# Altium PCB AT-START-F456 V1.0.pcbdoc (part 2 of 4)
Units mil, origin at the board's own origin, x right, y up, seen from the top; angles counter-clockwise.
Board outline 10942.5 x 3554 mil, 2 copper layers (Top Layer, Bottom Layer); 156 components, 201 nets, 759 pads, 796 vias.
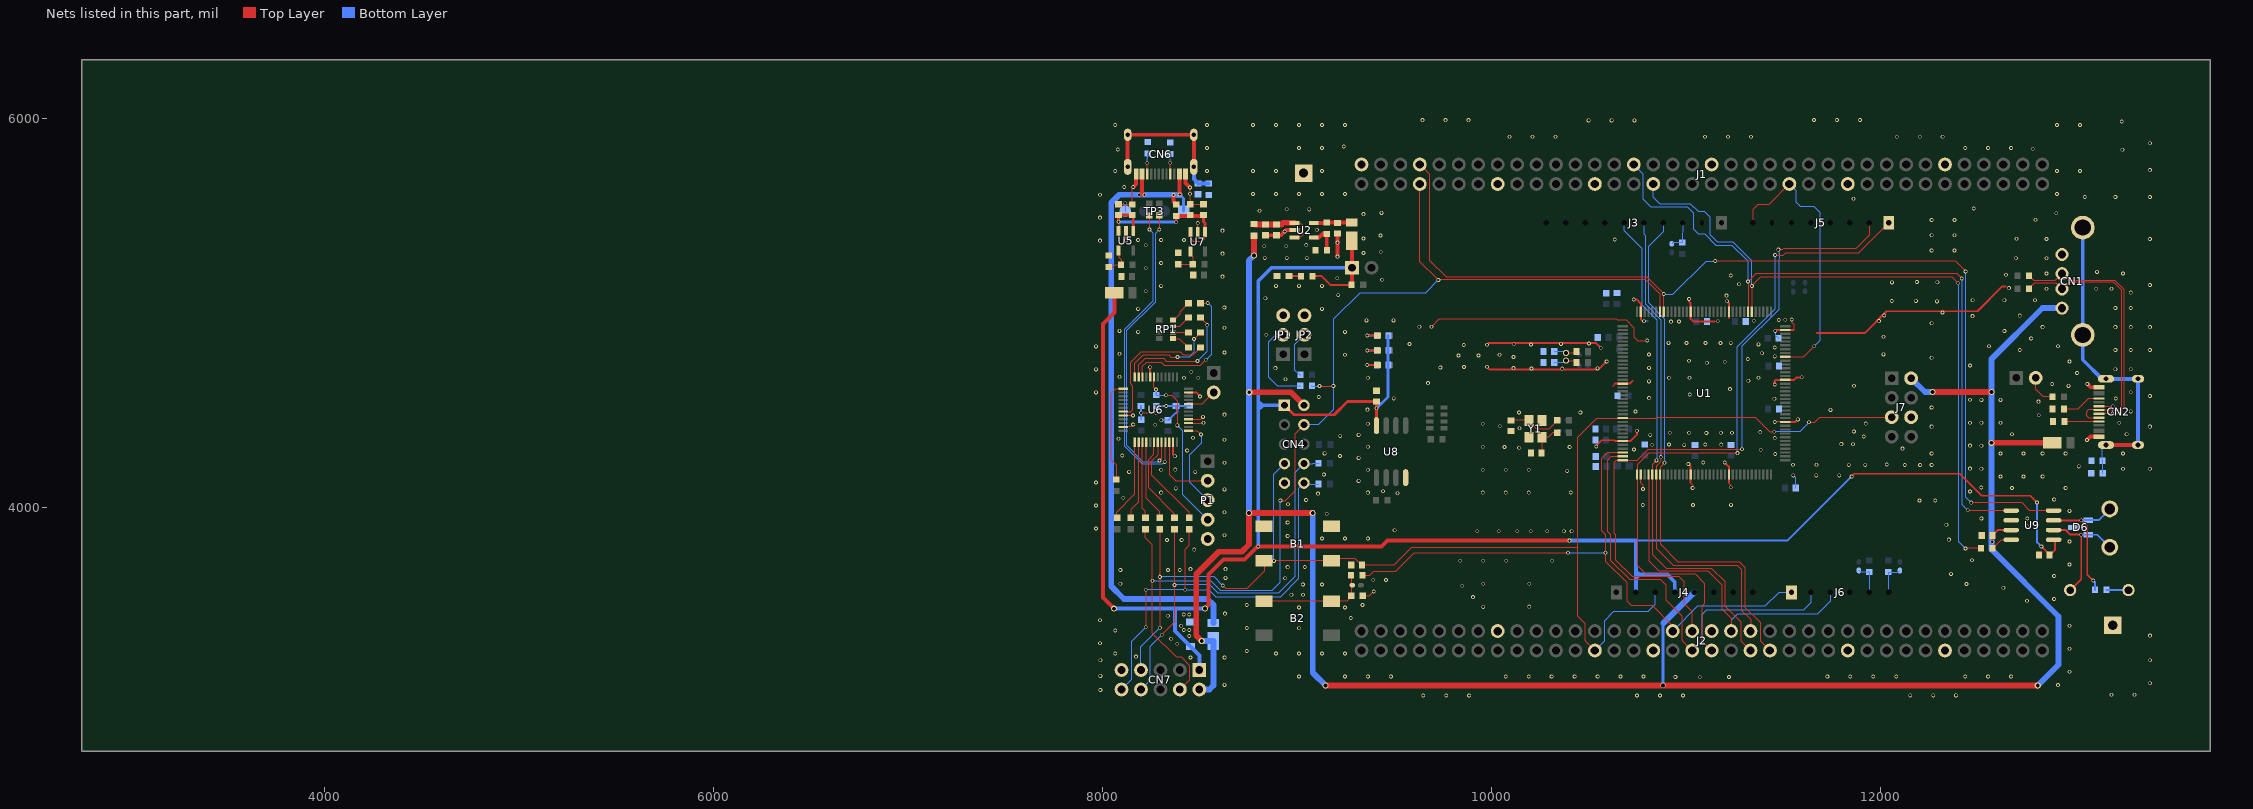
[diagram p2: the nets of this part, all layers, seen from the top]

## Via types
v1: diameter 19.7, hole 11.8, Top Layer to Bottom Layer, 419 vias
v2: diameter 19.68, hole 11.81, Top Layer to Bottom Layer, 364 vias
v3: diameter 31.5, hole 19.68, Top Layer to Bottom Layer, 12 vias
v4: diameter 27.56, hole 19.68, Top Layer to Bottom Layer, 1 vias

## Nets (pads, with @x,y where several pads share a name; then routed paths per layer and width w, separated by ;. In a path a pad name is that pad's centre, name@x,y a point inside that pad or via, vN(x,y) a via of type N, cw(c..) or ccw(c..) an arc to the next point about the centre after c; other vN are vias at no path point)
3V3: C13.1 C42.2 CN4.1 CN7.1 D1.1 D4.1 D5.1 J4.2 J4.4 JP3.1 R10.1 R17.1 R26.1 R27.1 R28.1 U8.8 U9.5 | length 11760.2
  Top Layer w10: R10.1@9075.76,5191.98 9124.16,5191.98 9169.26,5146.98 R17.1@9280.76,5146.98 ; v2(11848.96,4161.95) 11862.88,4175.87 12405.37,4175.87 12518.62,4062.61 12767.57,4062.61 v2(12802.57,4027.61) ; v2(12824.49,3801.51) 12825.48,3801.51 12860.91,3766.07 12860.91,3763.12 C42.2@12866.82,3757.22 12895.36,3785.76 12895.36,3828.97 U9.5@12887.72,3836.61
  Top Layer w15: CN4.1@8933.26,4527.98 8980.46,4480.48 9189.26,4479.18 9257.66,4547.38 9406.16,4547.38 9406.16,4512.98 9406.76,4512.38 U8.8@9406.16,4423.68
  Top Layer w20: v3(8056.02,3482.17) 7999.57,3538.62 7999.57,4945.41 8058.76,5004.61 D5.1@8058.76,5091.44 ; D5.1@8058.76,5107.05 D5.1@8058.76,5091.44 ; D5.1@8078.86,5111.53 D5.1@8058.76,5091.44 ; v3(8524.32,3482.61) 8542.32,3500.61 8542.32,3657.37 8620.57,3735.61 8728.41,3735.61 8794.76,3801.97 v2(8798.21,3801.97) 9432.21,3801.97 9462.21,3831.97 v2(10398.21,3831.97) ; D1.1@9280.21,5373.23 JP3.1@9280.21,5234.97 9280.16,5147.48 R17.1@9280.76,5146.98
  Bottom Layer w10: 10739.86,3831.98 11518.99,3831.98 v2(11848.96,4161.95) ; v2(12802.57,4027.61) 12802.57,3823.43 v2(12824.49,3801.51)
  Bottom Layer w15: v2@9406.76,4512.38 9465.36,4571.08 R28.1@9465.36,4886.28
  Bottom Layer w20: v3(8056.02,3482.17) 8056.47,3482.61 8362.66,3482.61 ; CN7.1@8495.46,3166.58 8495.46,3241.74 D4.1@8449.57,3287.62 8370.57,3366.62 8370.57,3474.71 8362.66,3482.61 ; v3(8524.32,3482.61) 8362.66,3482.61 ; v2@8798.26,3801.98 8798.26,4505.87 ; CN4.1@8933.26,4527.98 8817.56,4528.58 ; JP3.1@9280.21,5234.97 8867.26,5234.98 8798.26,5165.98 8798.26,4547.88 ; v2@10398.26,3831.98 10739.86,3831.98 10739.86,3674.68 ; J4.2@10739.86,3565.98 10739.86,3638.78 ; J4.4@10939.86,3565.98 10939.86,3619.38 10902.26,3656.98 10757.56,3656.98 ; 8798.26,4505.87 8817.56,4525.17 8817.56,4528.58 ; 8798.26,4505.87 8798.26,4547.88 ; 8798.26,4547.88 8817.56,4528.58 ; 10739.86,3638.78 10757.56,3656.98 ; 10739.86,3638.78 10739.86,3674.68 ; 10739.86,3674.68 10757.56,3656.98
  other v2: 9406.72,4512.39
5V: C41.2 CN1.1 CN4.2 CN7.2 D2.1 D3.1 F1.1 J4.5 J7.2 U9.3 | length 11648.9
  Top Layer w10: v2(12572.57,3826.61) 12573.13,3827.17 C41.2@12573.13,3858.61 12573.13,3860.58 12599.16,3886.61 U9.3@12669.42,3886.61
  Top Layer w30: v3(8507.66,3316.18) 8479.57,3344.27 8479.57,3658.61 8595.57,3774.61 8713.57,3774.61 8751.21,3812.25 v3(8751.21,3973.97) v3(9078.21,3973.97) ; v3(8752.21,4594.97) 8966.24,4594.97 CN4.2@9033.23,4527.98 ; v3@8776.26,5297.98 F1.1@8776.26,5399.98 ; v3(9144.75,3086.78) v3(12805.73,3086.78) ; v3@12263.57,4596.61 v3(12264.57,4595.61) v3(12567.57,4595.61) ; v3(12567.77,4334.82) 12879.89,4334.82 D2.1@12880.89,4335.82
  Bottom Layer w15: v4(10879.57,3087.61) 10879.26,3087.93 10879.26,3404.98 10881.26,3406.98
  Bottom Layer w30: CN7.2@8495.46,3066.58 8547.53,3066.58 8567.57,3086.61 D3.1@8567.57,3315.86 8507.97,3315.86 v3(8507.66,3316.18) ; v3(8751.21,3973.97) 8751.21,5272.97 v3(8776.21,5297.97) ; v3@9078.21,3973.93 9078.21,3153.33 v3(9144.75,3086.78) ; 10881.26,3406.98 J4.5@11039.86,3565.98 ; J7.2@12154.81,4666.56 12225.75,4595.61 v3(12264.57,4595.61) ; v3(12805.73,3086.78) 12912.57,3193.61 12912.57,3442.42 12567.77,3787.22 v3(12567.77,4334.82) 12567.57,4335.02 v3(12567.57,4595.61) 12567.57,4764.6 12830.47,5027.5 CN1.1@12930.72,5027.5
$2N452: C1.2 R1.1 Y1.1 | length 279.2
  Top Layer w6: C1.2@10097.57,4450.17 10097.82,4449.92 Y1.1@10190.1,4449.92 10190.1,4445.99 10231.48,4404.61 10291.04,4404.61 10335.91,4449.48 R1.1@10335.91,4450.61
$2N453: C2.2 R3.1 Y1.3 | length 170
  Top Layer w6: C2.2@10255.13,4282.61 10257.03,4284.52 Y1.3@10257.03,4363.3 10288.26,4363.3 10311.57,4386.61 R3.1@10335.91,4386.61
$2N511: C3.2 R5.1 X1.1 | length 120.3
  Top Layer w5.98: X1.1@10380.73,4796.85 10426.66,4796.85 R5.1@10434.27,4804.45
  Bottom Layer w5.98: C3.2@10319.95,4803.64 10373.94,4803.64 X1.1@10380.73,4796.85
$2N512: C4.2 R6.1 X1.2 | length 122.2
  Top Layer w5.98: X1.2@10380.73,4757.48 10424.51,4757.48 R6.1@10434.27,4747.72
  Bottom Layer w5.98: C4.2@10319.96,4748.08 10371.34,4748.08 X1.2@10380.73,4757.48
$2N701: JP1.2 R13.1 | length 455.4
  Bottom Layer w6: JP1.2@8926.26,4889.98 8887.16,4889.98 8850.26,4852.98 8850.26,4674.98 8897.16,4627.98 R13.1@9016.76,4627.98
$2N702: JP2.2 R14.1 | length 244.9
  Bottom Layer w6: R14.1@9017.76,4683.98 9011.76,4683.98 8984.26,4711.48 8984.26,4837.98 JP2.2@9036.26,4889.98
$3N58: C5.1 C6.1 F1.2 U2.1 U2.3 | length 369.5
  Top Layer w6: U2.1@8971.16,5465.98 9014.56,5464.58 9026.26,5452.98 9026.26,5402.98 9014.16,5390.98 U2.3@8984.26,5390.98
  Top Layer w30: F1.2@8776.26,5459.28 8778.36,5457.08 8836.21,5457.08 8891.21,5457.08 8917.86,5457.08 8926.66,5465.98 8971.16,5465.98 U2.1@8984.26,5465.98
$3N81: R15.1 R16.1 U2.4 | length 160.8
  Top Layer w20: U2.4@9084.26,5390.98 9111.16,5390.98 9130.76,5410.48 9150.26,5410.48 9150.26,5324.48 R15.1@9149.66,5323.98
$3N82: C7.1 D1.2 R16.2 U2.5 | length 196.6
  Top Layer w20: U2.5@9084.26,5465.98 9114.76,5465.98 9115.16,5465.48 9150.16,5465.48 9151.46,5466.68 D1.2@9280.21,5466.73
$3N119: LED1.1 R10.2 | length 64.5
  Top Layer w10: LED1.1@8956.26,5192.78 R10.2@9020.76,5191.98
$3N184: B2.2 B2.4 R18.2 R19.1 R20.1 | length 568
  Top Layer w6: B2.4@8828.03,3521.56 B2.2@9174.49,3521.56 9252.26,3521.58 9278.66,3547.98 9277.66,3548.98 R19.1@9277.66,3653.98
$3N504: LED2.1 R26.2 | length 104.4
  Top Layer w10: v2@9358.66,4734.58 9359.26,4735.18 LED2.1@9411.01,4735.2
  Bottom Layer w10: v2@9358.66,4734.58 9359.06,4734.98 R26.2@9410.36,4734.98
  other v2: 9358.65,4734.61
$3N505: LED3.1 R27.2 | length 104.1
  Top Layer w10: v2@9358.66,4809.98 LED3.1@9411.06,4810.18
  Bottom Layer w10: v2@9358.66,4809.98 R27.2@9410.36,4809.98
  other v2: 9358.65,4810
$3N506: LED4.1 R28.2 | length 104.1
  Top Layer w10: v2@9358.66,4886.28 LED4.1@9411.06,4886.48
  Bottom Layer w10: v2@9358.66,4886.28 R28.2@9410.36,4886.28
  other v2: 9358.65,4886.3
$3N17443: CN2.B5 R33.2 | length 202.1
  Top Layer w6: R33.2@12941.23,4508.61 13010.57,4508.61 13064.67,4562.72 CN2.B5@13120.94,4562.72
$3N17484: CN2.A5 R32.2 | length 177.7
  Top Layer w5.98: R32.2@12943.23,4444.61 CN2.A5@13120.94,4444.62
$3N17593: JP4.2 R34.1 | length 159.9
  Top Layer w5.98: JP4.2@12795.57,4668.61 12795.57,4611 12833.95,4572.61 R34.1@12881.91,4572.61
$3N25576: R90.2 U9.4 | length 114.4
  Top Layer w5.98: R90.2@12573.23,3792.61 12575.57,3792.61 12619.57,3836.61 U9.4@12669.42,3836.61
$3N25805: R89.1 SW1.2 | length 112.8
  Bottom Layer w10: R89.1@13160.23,3578.61 13271.57,3578.61 SW1.2@13272.57,3577.61
$4N269: J6.5 R56.2 R57.2 | length 163
  Bottom Layer w6: R56.2@11886.26,3678.68 11892.46,3672.48 11940.16,3672.48 J6.5@11939.86,3565.98
$4N270: J6.6 R58.2 R59.2 | length 168.5
  Bottom Layer w6: J6.6@12039.8,3565.97 12039.81,3667.56 R59.2@12037.06,3670.3 12089.36,3670.3 R58.2@12096.95,3677.89
$4N339: J3.3 R60.1 R61.2 | length 161.8
  Bottom Layer w6: R60.1@10926.16,5357.28 10926.16,5362.48 10979.26,5362.48 J3.3@10979.86,5465.98
$6N792: LD1.1 RP1.8 | length 121.7
  Top Layer w6: RP1.8@8360.2,4965.45 8363.16,4965.45 8397.25,4999.55 8397.25,5009.62 8439.43,5051.8 LD1.1@8439.43,5052.63
$6N793: LD2.1 RP1.7 | length 98.6
  Top Layer w6: RP1.7@8360.2,4933.96 8393.82,4933.96 8438.39,4978.53 LD2.1@8440.39,4978.53
$6N794: LD3.1 RP1.6 | length 80.6
  Top Layer w6: RP1.6@8360.2,4902.46 8415.6,4902.46 8416.43,4901.63 LD3.1@8440.43,4901.63
$6N795: LD4.1 RP1.5 | length 99
  Top Layer w6: RP1.5@8360.2,4870.97 8393.05,4870.97 8438.39,4825.63 LD4.1@8440.39,4825.63
$6N16959: C15.2 C16.2 C18.2 C19.2 F2.2 U5.1 U5.3 U7.1 U7.3 | length 955.4
  Top Layer w6: v2(8079.97,5471.01) 8079.97,5424.64 U5.3@8080.56,5424.05 ; U7.3@8449.34,5418.39 8449.34,5386.85 8465.17,5371.01 8510.77,5371.01 8524.34,5384.58 U7.1@8524.34,5418.39
  Top Layer w15: v2(8079.97,5471.01) 8079.97,5504.25 8077.97,5506.25 8149.57,5506.25 C19.2@8150.37,5505.45 8155.56,5500.26 U5.1@8155.56,5424.05 ; v2(8376.76,5469.02) 8376.76,5500.59 F2.2@8377.56,5501.39 ; C16.2@8517.56,5506.49 8517.56,5471.42 8524.34,5464.65 U7.1@8524.34,5418.39
  Top Layer w20: F2.2@8377.56,5501.39 8512.46,5501.39 C16.2@8517.56,5506.49
  Bottom Layer w15: v2(8079.97,5471.01) 8081.17,5469.81 8375.97,5469.81 v2(8376.76,5469.02)
$6N17598: R43.2 R49.1 U7.4 | length 144.7
  Top Layer w6: R49.1@8387.57,5252.95 8439.57,5252.95 8440.03,5253.41 R43.2@8461.9,5253.41 8461.9,5290.28 8449.34,5302.85 U7.4@8449.34,5318.39
$6N17675: R50.2 R51.1 U5.4 | length 146.5
  Top Layer w6: R51.1@8029.57,5238.95 8052.89,5238.95 8064.98,5251.05 R50.2@8092.9,5251.05 8092.9,5275.68 8080.56,5288.02 U5.4@8080.56,5324.05
ATLINK_5V: CN6.A4B9 CN6.B4A9 D3.2 F2.1 TP3.1 | length 3362.8
  Top Layer w20: CN6.B4A9@8200.71,5717.9 8200.71,5609.88 8201.17,5609.41 ; v2(8362.76,5609.37) 8362.76,5575.52 F2.1@8377.56,5560.71 ; CN6.A4B9@8393.71,5717.9 8394.27,5717.34 v2(8394.27,5611.13)
  Bottom Layer w15: v2(8394.27,5611.13) 8414.58,5590.82 TP3.1@8414.58,5526.61
  Bottom Layer w30: v2(8394.27,5611.13) 8392.51,5609.37 v2(8362.76,5609.37) 8361.51,5610.61 v2(8213.24,5610.61) v2(8186.47,5610.61) 8083.57,5610.61 8042.25,5569.3 8042.25,3597.93 8108.3,3531.88 8537.57,3531.88 8567.57,3501.88 D3.2@8567.57,3409.36
ATLK_BOOT0: R45.1 U6.27 | length 395.7
  Top Layer w6: U6.27@8203.01,4337.98 8202.96,3998.78 8218.46,3983.38 R45.1@8218.46,3948.68
ATLK_NRST: R46.1 U6.28 | length 419.2
  Top Layer w6: U6.28@8222.69,4337.98 8222.66,4049.48 8292.46,3979.78 R46.1@8292.46,3947.68
ATLK_RX: CN4.10 CN7.10 R25.1 R48.2 | length 2281.5
  Top Layer w6: v2(8219.86,3386.38) 8219.86,3578.78 v2(8220.26,3579.18) ; v2@8425.16,3576.68 v2(8422.66,3579.18) 8422.66,3788.08 8443.66,3809.08 R48.2@8443.66,3892.68
  Bottom Layer w6: CN7.10@8095.46,3066.58 8145.96,3117.18 8145.96,3312.48 v2(8219.86,3386.38) ; v2(8220.26,3579.18) v2(8422.66,3579.18) 8545,3579.18 8579.46,3544.73 8913.43,3544.73 9007.59,3638.89 9007.59,4102.34 CN4.10@9033.23,4127.98 ; CN4.10@9061.16,4128.18 9066.16,4123.08 R25.1@9110.16,4123.08
ATLK_SWCLK: R41.1 U6.25 | length 427
  Top Layer w6: R41.1@8070.46,3949.58 8070.46,3979.08 8163.66,4072.28 U6.25@8163.66,4337.98
ATLK_SWDIO: R44.1 U6.26 | length 404.5
  Top Layer w6: R44.1@8144.46,3949.58 8144.46,3993.08 8183.36,4031.98 U6.26@8183.36,4337.98
ATLK_SWO: R52.1 U6.13 | length 530.4
  Top Layer w6: R52.1@8070.26,4142.58 8070.26,4218.73 8042.65,4246.34 8042.65,4589.69 8066.53,4613.58 U6.13@8104.58,4613.57
ATLK_TX: CN4.8 CN7.8 R24.1 R47.2 | length 2247.2
  Top Layer w6: v2(8302.46,3348.18) 8367.5,3413.22 v2(8367.5,3603.41) 8367.5,3846.62 8367.66,3846.78 R47.2@8367.66,3892.68
  Bottom Layer w6: CN7.8@8195.43,3066.63 8244,3115.2 8244,3289.72 v2(8302.46,3348.18) ; v2(8367.5,3603.41) 8368.11,3604.03 8550.15,3604.03 8592.12,3562.06 8900.43,3562.06 8985.14,3646.77 8985.14,4179.88 CN4.8@9033.23,4227.98 ; CN4.8@9033.26,4227.98 9078.86,4227.98 9080.96,4229.98 R24.1@9110.76,4229.98
BOOT0: CN4.4 CN7.4 J1.66 R13.2 R45.2 U1.138 | length 5703.8
  Top Layer w6: R45.2@8218.66,3892.68 8218.66,3846.33 8253.97,3811.01 8253.97,3355.87 8378.26,3231.58 8403.96,3231.58 8446.06,3189.58 8446.06,3117.18 CN7.4@8395.46,3066.58 ; v2(8912.21,4037.97) 8937.81,4037.97 8987.5,4087.66 8987.5,4382.24 CN4.4@9033.23,4427.98 ; v2(9113.66,4626.6) v2(9184.53,4626.6) ; J1.66@9629.16,5665.18 9629.16,5266.98 v2(9724.26,5171.98) 10791.16,5171.98 10863.86,5099.28 U1.138@10863.86,5008.28
  Bottom Layer w6: v2(8254.21,3625.97) 8554.21,3625.97 8603.22,3576.97 8870.92,3576.97 8912.21,3618.25 v2(8912.21,4037.97) ; CN4.4@9033.26,4427.98 9105.76,4428.18 9183.26,4505.68 9183.26,4968.98 9319.14,5104.86 9657.14,5104.86 v2(9724.26,5171.98) ; R13.2@9071.76,4627.98 9073.06,4626.58 v2(9113.66,4626.6)
CAN1_RX: J1.42 R90.1 U1.114 | length 3578
  Top Layer w5.98: v2(11336.13,5141.22) 11382.62,5187.7 12364.76,5187.7 v2(12397.21,5155.25) ; v2(12434.17,3791.7) 12435.09,3792.61 R90.1@12513.91,3792.61
  Top Layer w6: v2(11336.13,5141.22) 11336.08,5008.45 U1.114@11336.26,5008.28
  Bottom Layer w6: J1.42@10829.16,5665.68 10829.16,5596.98 10864.26,5561.98 11022.26,5561.98 11062.16,5521.98 11094.26,5521.98 11122.26,5493.98 11122.26,5404.58 11160.26,5366.58 11239.56,5366.58 11336.08,5270.05 v2(11336.13,5141.22) ; v2(12397.21,5155.25) 12398.55,5153.92 12398.55,3827.32 v2(12434.17,3791.7)
CAN1_STB: J1.65 U1.137 U9.8 | length 5167.7
  Top Layer w5.98: v2(11147.57,5269.61) 11149.75,5267.43 12384.01,5267.43 v2(12435.29,5216.16) ; v2(12464,4027.43) 12465.81,4025.61 12726.6,4025.61 12765.6,3986.61 U9.8@12887.72,3986.61
  Top Layer w6: J1.65@9629.16,5765.68 9680.26,5714.58 9680.26,5271.88 9766.26,5185.98 10799.36,5185.98 10883.56,5101.68 U1.137@10883.56,5008.28
  Bottom Layer w5.98: v2(10883.57,5099.61) 10930.57,5099.61 11100.57,5269.61 v2(11147.57,5269.61) ; v2(12435.29,5216.16) 12435.49,5215.96 12435.49,4055.94 v2(12464,4027.43)
CAN1_TX: J1.43 U1.115 U9.1 | length 3734.5
  Top Layer w5.98: v2(11316.43,5164.07) 11359.13,5206.77 12388.83,5206.77 v2(12415.61,5179.99) ; v2(12446.02,3988.17) 12447.57,3986.61 U9.1@12669.42,3986.61
  Top Layer w6: v2(11316.43,5164.07) 11316.38,5008.45 U1.115@11316.56,5008.28
  Bottom Layer w5.98: v2(12415.61,5179.99) 12417.46,5178.14 12417.46,4016.73 v2(12446.02,3988.17)
  Bottom Layer w6: J1.43@10729.16,5765.68 10778.26,5716.58 10778.26,5585.88 10818.26,5545.98 11006.26,5545.98 11036.26,5515.98 11036.26,5433.88 11063.76,5406.38 11095.86,5406.38 11153.26,5348.98 11235.96,5348.98 11316.38,5268.55 v2(11316.43,5164.07)
CAN_H: CN8.2 D6.1 R89.2 U9.7 | length 700.6
  Top Layer w10: U9.7@12887.72,3936.61 v2(13029.57,3936.61) 13060.57,3905.61 13060.57,3657.61 v2(13091.57,3626.61)
  Bottom Layer w10: v2(13029.57,3936.61) 13029.97,3937.02 13118.55,3937.02 CN8.2@13176.57,3995.04 ; v2(13091.57,3626.61) 13100.91,3617.27 R89.2@13100.91,3578.61
CAN_L: CN8.1 D6.2 SW1.1 U9.6 | length 634.1
  Top Layer w10: U9.6@12887.72,3886.61 12949.57,3886.61 12973.57,3862.61 v2(13029.57,3862.61) 13029.57,3634.61 SW1.1@12972.57,3577.61
  Bottom Layer w10: v2(13029.57,3862.61) 13029.97,3862.21 13112.55,3862.21 CN8.1@13176.57,3798.19
CC1: CN6.A5 R86.1 | length 101.4
  Top Layer w6: v1(8345.57,5774.61) 8346.41,5773.78 CN6.A5@8346.41,5717.9
  Bottom Layer w6: v1(8345.57,5774.61) R86.1@8345.57,5818.95
CC2: CN6.B5 R87.1 | length 106.2
  Top Layer w6: v1(8227.57,5772.61) 8228.31,5771.88 CN6.B5@8228.31,5717.9
  Bottom Layer w6: v1(8227.57,5772.61) 8227.57,5799.08 8229.57,5801.08 R87.1@8229.57,5822.95
EGND: C20.2 CN6.13 CN6.14 CN6.15 CN6.16 R88.1 | length 818.4
  Top Layer w20: CN6.14@8127.11,5753.9 CN6.16@8127.11,5918.5 CN6.15@8467.31,5918.5 CN6.13@8467.31,5753.9
  Bottom Layer w20: CN6.13@8467.31,5753.9 8467.31,5690.44 C20.2@8489.57,5668.17 8543.47,5668.17 R88.1@8543.57,5668.27
EGND1: C21.1 CN1.SH1 CN1.SH2 CN2.13 CN2.14 CN2.15 CN2.16 R35.2 | length 1662.3
  Top Layer w20: CN2.13@13156.94,4323.72 CN2.15@13321.54,4323.72
  Bottom Layer w5.98: R35.2@13140.23,4178.61 13138.13,4180.71 C21.1@13138.13,4242.61 13138.13,4304.91 CN2.13@13156.94,4323.72
  Bottom Layer w20: CN1.SH1@13037.41,5440.9 CN1.SH2@13037.41,4889.71 13037.41,4761.79 13135.29,4663.92 CN2.14@13156.94,4663.92 CN2.16@13321.54,4663.92 CN2.15@13321.54,4323.72
GND: B1.2 B1.4 C1.1 C2.1 C3.1 C4.1 C5.2 C6.2 C7.2 C8.1 C9.1 C10.1 C11.1 C12.1 C13.2 C14.1 C15.1 C16.1 C17.1 C18.1 C19.1 C20.1 C21.2 C22.1 C23.2 C24.2 C25.2 C26.2 C27.2 C28.2 C29.2 C30.2 C31.2 C32.2 C33.2 C34.2 C35.2 C36.2 C37.2 C38.2 C39.2 C40.2 C41.1 C42.1 CN1.4 CN2.A1B12 CN2.B1A12 CN4.9 CN6.A1B12 CN6.B1A12 CN7.9 D4.2 D6.3 J1.11 J1.22 J1.35 J1.48 J1.58 J1.71 J2.16 J2.31 J2.38 J2.51 J2.61 J3.7 J4.6 J4.7 J7.6 JP1.3 JP2.3 LED1.2 P1.5 R15.2 R18.1 R32.1 R33.1 R35.1 R49.2 R51.2 R86.2 R87.2 R88.2 T1.1 T2.1 TP3.4 U1.16 U1.31 U1.38 U1.51 U1.61 U1.83 U1.94 U1.107 U1.120 U1.130 U1.143 U2.2 U5.2 U6.8 U6.20 U6.23 U6.35 U6.39 U6.40 U6.47 U7.2 U8.4 U9.2 Y1.2 Y1.4 | length 7348.2
  Top Layer w5.98: v1(9689.57,4931.61) 9729.57,4971.61 10638.94,4971.61 10643.09,4967.46
  Top Layer w6: C18.1@8080.37,5561.37 8149.57,5561.37 C19.1@8150.37,5560.57 8150.37,5644.21 v2(8156.11,5649.96) ; U6.23@8104.58,4416.72 8142.48,4416.72 v2(8155.17,4429.41) ; U6.20@8104.58,4475.78 8153.2,4475.78 v2(8153.97,4475.01) ; v2(8196.37,4489.41) 8197.17,4488.61 8272.57,4488.61 v2(8273.57,4487.61) ; U6.39@8439.23,4436.41 8515.15,4436.41 v2(8516.94,4438.2) ; U6.40@8439.23,4456.09 8501.93,4456.09 v2(8514.03,4468.19) ; v2(8447.17,5647.41) v1(8447.17,5615.61) 8447.17,5584.75 8448.56,5583.36 C15.1@8448.56,5561.61 C16.1@8517.56,5561.61 ; v2(8487.17,5464.21) 8487.34,5464.05 U7.2@8487.34,5418.39 ; R18.1@9335.87,3547.97 9369.42,3547.97 v1(9391.96,3570.51) ; 10618.26,4623.08 10634.36,4639.18 ; 10643.09,4967.46 10689.19,4967.46 10729.37,4927.27 10729.37,4880.81 10749.38,4860.8 v1(10798.05,4860.8) ; U1.38@10765.46,4171.68 10765.46,4128.38 10776.57,4117.27 v1(10776.57,4097.61) ; U1.51@11021.36,4171.68 11021.36,4127.78 11031.5,4117.74 ; v1(11031.57,4102.61) 11031.57,4117.67 ; 11218.16,4134.08 11218.16,4127.28 11227.57,4117.87 v1(11227.57,4106.61) ; v1(11453.48,4442.3) U1.83@11508.48,4442.35 ; v1(11541.13,4968.64) 11541.13,4954.35 11551.32,4944.15 11551.32,4916.85 11549.26,4914.78
  Top Layer w10: U6.8@8242.36,4672.68 8242.43,4672.75 v2(8242.43,4723.22) ; U6.35@8360.49,4337.98 8360.49,4275.35 v2(8369.66,4266.18) ; U6.47@8439.26,4593.88 8478.39,4594.19 v2(8499.17,4573.41) ; v1(9973.91,4725.6) 9988.55,4710.97 v1@10366.76,4710.97 ; v1(9974.68,4839.18) 9982.5,4847.01 10535.77,4847.01 v1(10558.92,4823.86) ; v1(10361.31,4716.43) v1@10366.76,4710.97 ; v1@10538.26,4321.28 10565.16,4348.18 10628.39,4348.18 10632.7,4343.88 U1.31@10671.86,4343.93 10711.26,4343.88 10744.91,4377.54 v1(10744.91,4396.83) ; v1(10589.45,4753.04) 10553.99,4717.58 v1(10542.74,4717.58) 10536.13,4710.97 v1@10366.76,4710.97 ; 10631.46,4639.18 10634.36,4639.18 U1.16@10671.86,4639.2 10708.16,4639.18 10721.56,4652.58 ; v1(10729.21,5072.19) 10743.36,5072.19 10765.36,5050.18 U1.143@10765.37,5008.31 10765.36,4968.98 v1@10772.76,4961.68 ; v1(11009.57,4225.61) 11021.26,4213.93 U1.51@11021.27,4171.68 11021.26,4129.48 ; v1@11011.86,5076.32 11011.86,5061.58 11021.36,5052.18 11021.36,5008.31 11021.36,4972.08 11034.26,4959.18 11143.06,4959.18 ; v1(11196.57,4233.61) 11218.16,4212.03 11218.16,4171.68 11218.16,4134.08 ; v1@11214.76,5056.08 11218.16,5052.78 11218.16,5008.31 11218.16,4975.38 ; v1(11453.53,4634.21) 11453.19,4634.55 11453.19,4651.81 11460.26,4658.88 U1.94@11508.48,4658.89 11553.16,4658.88 11565.89,4671.61 v2(11592.57,4671.61) ; v1(11456.57,4910.61) 11456.57,4914.78 U1.107@11508.48,4914.79 11549.26,4914.78 ; U1.83@11508.56,4442.28 11559.66,4442.28 v1(11572.76,4455.38) ; 11670.03,4899.32 11916.31,4899.32 12028.39,5011.4 12496.18,5011.4 12624.15,5139.36 12639.71,5139.36
  Top Layer w15: U5.2@8118.56,5424.05 8119.17,5423.44 v2(8119.17,5375.81)
  Top Layer w20: v2(8156.11,5649.96) 8170.41,5664.25 CN6.B1A12@8170.41,5717.9 ; CN6.A1B12@8424.21,5717.9 8424.21,5670.38 v2(8447.17,5647.41) ; C5.2@8836.21,5402.05 C6.2@8891.21,5402.05 8915.36,5402.08 v1(8934.33,5421.12) 8942.16,5428.98 U2.2@8984.26,5428.98 ; C7.2@9206.16,5410.48 v1(9206.16,5364.21) v1(9206.16,5291.98) v1@9206.26,5291.98 ; v1(13059.04,4349.42) 13076.44,4366.82 CN2.A1B12@13120.94,4366.82 ; v1(13061.04,4637.42) 13077.84,4620.62 CN2.B1A12@13120.94,4620.62
  Bottom Layer w5.98: v1(11549.18,4167.71) 11561.77,4155.12 C29.2@11561.77,4101.97
  Bottom Layer w6: TP3.4@8114.58,5526.61 v1(8114.57,5566.61) ; v2(8273.57,4487.61) 8273.97,4488.01 C22.1@8273.97,4524.65 ; v2(8300.41,4450.97) C11.1@8335.17,4450.97 ; v1(10781.23,4959.9) 10802.13,4959.9 10802.77,4959.26 ; v1(11456.57,4910.61) 11456.57,4889.17 C32.2@11473.13,4872.61
  Bottom Layer w10: C12.1@8196.37,4524.65 v2(8196.37,4489.41) 8196.77,4489.01 C10.1@8196.77,4453.77 ; C22.1@8273.97,4524.65 v2(8325.27,4524.65) C9.1@8376.37,4524.65 ; C11.1@8335.17,4450.97 8371.21,4487.01 8375.17,4487.01 8382.24,4494.09 8382.24,4504.09 8376.37,4509.96 C9.1@8376.37,4524.65 ; C9.1@8376.37,4525.05 C9.1@8376.37,4524.65 ; C8.1@8446.37,4525.85 8418.65,4525.85 8417.45,4524.65 C9.1@8376.37,4524.65
  other v1: 9646.44,3035.82 9764.55,3035.82 9882.66,3035.82 10745.74,3035.82 10863.85,3035.82 10981.96,3035.82 12150.21,3036.6 12268.32,3036.6 12386.43,3036.6 7986.57,3063.61 12910.14,3088.92 8624.57,3090.61 11068.29,3129.68 10942.92,3130.71 11218.56,3130.71 9007.66,3133.82 9243.88,3133.82 9361.99,3133.82 9480.1,3133.82 10070.65,3133.82 10188.76,3133.82 10306.87,3133.82 10424.98,3133.82 10543.09,3133.82 10661.2,3133.82 10779.31,3133.82 11724.2,3133.82 11842.31,3133.82 11960.42,3133.82 12078.53,3133.82 12432.86,3133.82 12550.97,3133.82 12669.08,3133.82 7986.57,3136.61 7986.57,3216.61 8449.57,3231.61 8625.57,3231.61 8169.57,3235.61 8062.78,3251.94 8889.55,3251.94 9007.66,3251.94 9125.77,3251.94 9243.88,3251.94 8739.57,3264.39 8382.07,3302.11 7984.57,3304.39 8350.57,3327.61 8443.57,3341.61 13383.27,3343.44 8062.78,3370.05 8415.07,3372.14 8443.57,3372.61 9008.57,3381.61 8739.57,3382.5 8402,3394.41 7984.57,3422.5 9273.57,3434.61 8333.57,3445.61 8415.57,3452.61 8443.57,3452.61 8627.57,3456.61 9007.66,3488.16 9243.88,3488.16 9955.57,3491.61 10191.55,3492.51 8739.57,3500.61 9334.55,3501.51 12751.19,3523.27 9902.57,3541.61 8968.57,3553.61 9028.57,3553.61 12629.27,3589.34 9847.57,3599.61 9027.66,3606.27 9125.77,3606.27 12439.47,3609 8089.57,3610.61 9955.33,3610.62 10191.55,3610.62 9455.57,3629.61 9389.57,3630.61 8936.59,3638.67 8629.57,3640.61 8089.57,3680.61 8334.57,3680.61 8394.57,3680.61 8449.57,3685.61 8629.57,3685.61 8949.57,3695.61 9037.57,3696.61 9837.22,3728.73 9955.33,3728.73 10073.44,3728.73 10309.66,3728.73 8469.57,3785.61 8329.57,3835.61 8404.57,3835.61 9125.77,3842.49 9243.88,3842.49 9361.99,3842.49 8949.57,3855.61 8624.57,3859.39 9924.57,3880.61 10034.57,3880.61 10129.57,3880.61 10199.57,3880.61 10284.57,3880.61 10369.57,3880.61 10409.57,3880.61 9499.57,3885.61 7964.57,3894.39 8949.57,3925.61 9150.77,3970.6 8624.57,3977.5 7964.57,4012.5 10775.57,4015.31 11033.65,4015.54 11228.8,4015.85 8951.08,4019.38 12279.22,4038.45 9044.57,4040.61 8104.57,4052.5 9105.77,4073.71 9514.57,4075.61 8299,4078.71 9361.99,4078.71 9952.54,4078.71 10070.65,4078.71 10188.76,4078.71 10404.57,4079.39 9439.57,4085.61 8624.57,4095.61 8374.57,4100.61 7964.57,4130.61 9314.57,4139.39 11667.29,4167.71 11785.4,4167.71 9135.77,4171.82 8134.57,4185.61 8474.57,4185.61 10386.94,4190.74 8299,4196.82 8371.4,4197.15 9361.99,4196.82 9952.54,4196.82 10070.65,4196.82 10188.76,4196.82 13016.84,4213.95 11547.64,4221.77 11668.11,4222.05 11833.98,4221.52 11919.21,4221.67 12029.3,4223.51 8624.57,4232.5 11086.46,4234.02 9314.57,4257.5 9218.34,4266.61 8099.57,4269.39 11456.18,4277.39 9139.57,4280.61 8432.74,4294.95 11381.5,4299.17 10730.04,4301.05 12110.21,4304.89 10139.64,4309.43 10064.81,4313.39 10399.24,4313.56 9361.99,4314.93 9952.54,4314.93 10536.27,4315.64 10988.84,4324.34 10823.72,4325.3 11178.64,4325.5 10909.7,4325.83 11096.88,4325.83 11796.21,4328.23 11856.41,4327.54 8624.57,4350.61 8079.57,4355.61 11453.44,4358.89 8463.33,4361.23 11911.3,4366.97 9219.57,4370.61 9314.57,4375.61 10813.35,4375.83 11102.16,4385 10914.13,4386.53 11013.73,4387.03 11176.75,4386.64 11234.34,4386.64 11378.97,4389.82 11860.56,4393.27 10141.94,4409.99 10040.24,4419.68 8269,4428.04 9361.99,4433.04 9952.54,4433.04 11921.44,4433.4 8625.22,4479.93 10454.31,4490.33 10138.63,4491.28 10738.1,4495.53 11740.53,4504.27 9359.57,4505.61 11451.68,4561.79 9495.17,4563.45 10808.14,4564.69 9109.57,4570.61 11016.87,4583.72 7964.57,4594.39 11224.09,4610.88 11861.61,4628.12 9671.57,4641.61 10807.75,4650.9 11318.07,4653.66 8938.27,4661.7 8417.11,4669.26 9361.99,4669.26 10910.91,4669.26 11015.53,4669.26 11369.87,4669.26 8489.51,4669.59 8084.57,4674.39 8454.25,4700 7964.57,4712.5 10202.88,4716.92 8886.25,4718.87 10110.79,4718.95 10807.6,4720.14 9734.57,4722.61 9855.76,4724.84 11104.74,4746.83 11197.11,4751.82 11013.41,4757.21 11315.3,4766.21 10110.53,4776.01 11453.53,4779.43 9930.71,4783.37 9827.67,4784.29 9243.88,4787.37 10038.18,4788.03 10807.5,4788.89 12012.44,4789.56 8084.57,4792.5 11387.57,4795.61 8624.57,4799.39 11453.53,4824.94 7964.57,4830.61 9855.25,4837.91 10111.81,4841.3 11370.06,4841.01 9575.57,4842.61 10354.49,4843.53 10499,4845.65 11000.57,4847.61 11097.57,4847.61 11174.57,4847.61 10907.57,4848.61 11227.57,4848.61 12012.54,4880.38 8839.57,4890.61 8180.89,4905.48 9243.88,4905.48 8084.57,4910.61 8624.57,4926.25 9626.57,4931.61 10919.94,4958 10961.57,4958.61 11160.57,4959.61 11345.57,4962.61 9355.15,4964.33 9493.64,4964.29 11474.74,4966.62 11507.95,4967.22 8180.89,5023.59 9125.77,5023.59 8624.26,5030.62 11207.57,5062.61 12055.51,5063.95 12179.38,5064.84 11013.57,5074.61 8834.96,5078.07 11205.57,5091.61 9209.57,5095.61 8219.57,5114.39 8299,5141.7 8889.55,5141.7 9007.66,5141.7 9125.77,5141.7 12056.43,5159.96 12184.54,5161.52 9435.18,5173.68 9204.57,5180.61 8614.57,5189.39 8219.57,5232.5 8299,5259.81 8831.46,5285.61 8944.57,5285.61 9047.68,5285.61 8614.57,5307.5 9339.57,5310.61 9428.04,5317.21 8829.57,5345.61 8942.68,5345.61 8219.57,5350.61 9045.17,5351.15 7984.57,5374.39 8180.89,5377.92 8299,5377.92 8417.11,5377.92 10631.33,5379.73 12696.74,5383.89 9339.57,5384.93 9427.35,5400.89 8614.57,5425.61 9099.57,5430.61 12793.91,5482.06 7984.57,5492.5 9339.57,5510.61 12900.76,5515.24 9431.5,5517.07 8804.71,5527.77 9060.59,5535.15 8944.57,5535.61 11859.02,5590.1 7984.57,5610.61 8771.44,5614.14 8889.55,5614.14 9007.66,5614.14 9125.77,5614.14 9243.88,5614.14 12905.3,5614.14 8109.57,5650.61 8062.78,5732.25 8535.22,5732.25 8771.44,5732.25 8889.55,5732.25 9125.77,5732.25 12905.3,5732.25 13023.41,5732.25 13240.91,5841.93 8076.21,5843.18 12780.53,5846.89 8535.22,5850.36 9007.66,5850.36 9125.77,5850.36 12432.86,5850.36 12550.97,5850.36 12669.08,5850.36 9237.66,5857.97 11095.21,5908.35 11213.32,5908.35 11331.43,5908.35 12080.8,5908.48 12198.91,5908.48 12317.02,5908.48 10089.92,5908.57 10208.03,5908.57 10326.14,5908.57 8062.78,5968.47 8535.22,5968.47 8771.44,5968.47 8889.55,5968.47 9007.66,5968.47 9125.77,5968.47 9243.88,5968.47 12905.3,5968.47 13023.41,5968.47 13237.8,5987.23 10497.05,5992.74 10615.16,5992.74 10733.27,5992.74 9642.7,5994.01 9760.81,5994.01 9878.92,5994.01 11655.09,5994.49 11773.2,5994.49 11891.31,5994.49
  other v2: 13185.48,3039.98 13303.59,3039.98 13382.33,3099.04 12968.94,3158.09 13382.33,3217.15 12968.94,3276.21 12968.94,3394.32 12890.2,3532.11 12890.2,3650.22 12359.9,3661.08 12968.94,3709.28 12468.18,3730.97 12968.94,3827.39 12349.08,3837.27 12752.4,3906.13 12336.28,3914.05 12516.18,3945.5 12752.4,3945.5 12968.94,3984.87 12197.49,4038.07 12890.2,4043.92 12458.09,4084.15 12673.66,4102.98 12949.25,4102.98 12515.32,4105.13 12614.61,4162.03 12732.72,4162.03 12831.14,4162.03 12516.18,4201.4 13244.53,4201.4 13382.33,4201.4 12458.09,4202.26 12122.48,4221.09 12201.22,4221.09 12260.28,4221.09 12260.28,4280.14 12614.61,4280.14 12732.72,4280.14 12831.14,4280.14 12949.25,4280.14 13244.53,4280.14 12458.09,4320.37 12516.18,4319.51 12673.66,4378.57 13262.9,4378.57 12260.28,4417.94 13382.33,4417.94 12458.09,4438.48 12516.18,4437.62 12614.61,4437.62 13224.85,4437.62 12811.46,4476.99 13283.9,4496.68 12260.28,4516.36 12809.57,4546.61 12516.18,4555.73 12614.61,4555.73 12458.09,4556.59 13207.16,4562.73 13382.33,4575.42 13283.9,4595.1 12964.57,4627.61 12880.2,4637.16 13008.31,4693.53 13205.16,4713.21 13283.9,4713.21 12457.13,4732.9 12968.94,4752.58 12260.28,4772.27 12713.03,4811.64 13205.16,4811.64 13283.9,4811.64 13382.33,4811.64 12555.55,4831.32 12909.88,4831.32 10200.86,4840.86 12772.09,4870.69 12634.29,4910.06 12831.14,4929.75 13205.16,4929.75 13283.9,4929.75 13382.33,4929.75 12260.28,4949.43 11989.07,4960.59 12470.57,4986.33 12713.03,4988.8 12017.05,4989.66 12315.76,5005 13205.16,5028.17 13283.9,5028.17 12287.78,5062.1 12471.28,5067.73 12634.29,5067.54 12791.77,5067.54 13283.9,5106.91 12850.83,5126.6 13106.73,5126.6 13185.48,5126.6 12657.63,5130.15 13382.33,5146.28 11270.69,5150.4 12289.94,5160.77 11227.73,5195.04 12642.57,5198.98 12850.83,5205.34 13244.53,5205.34 13110.61,5213.86 12693.35,5284.08 12850.83,5284.08 12260.28,5323.45 12378.39,5323.45 12850.83,5382.5 13382.33,5382.5 12260.28,5402.19 12378.39,5402.19 12260.28,5480.93 12378.39,5480.93 12476.81,5539.98 13047.68,5599.04 13205.16,5599.04 13382.33,5599.04 13382.33,5736.84 13382.33,5874.63
LD1: LD1.2 U6.10 | length 760.9
  Top Layer w6: U6.10@8203.01,4672.63 8203.01,4728.05 8223.97,4749.01 8299.93,4749.01 8315.93,4733.01 8499.57,4733.01 v2(8528.37,4761.81) ; LD1.2@8500.43,5052.63 8537.59,5052.63 v2(8538.77,5053.81)
  Bottom Layer w6: v2(8528.37,4761.81) 8530.37,4761.81 8558.77,4790.21 8558.77,5033.81 v2(8538.77,5053.81)
LD2: LD2.2 U6.11 | length 643.9
  Top Layer w6: U6.11@8183.32,4672.63 8183.32,4735.97 8216.77,4769.41 8312.03,4769.41 8326.03,4755.41 v2(8485.57,4755.41) ; LD2.2@8501.39,4978.53 8536.37,4943.56 v2(8536.37,4939.81)
  Bottom Layer w6: v2(8485.57,4755.41) 8536.37,4806.21 v2(8536.37,4939.81)
LD3: LD3.2 U6.12 | length 524.6
  Top Layer w6: U6.12@8163.64,4672.63 8163.64,4744.28 8207.17,4787.81 8337.17,4787.81 8349.13,4775.86 v2(8382.95,4775.86) ; v2(8467.97,4868.61) 8468.42,4868.61 LD3.2@8501.43,4901.63
  Bottom Layer w6: v2(8382.95,4775.86) 8443.61,4775.86 8467.97,4800.21 v2(8467.97,4868.61)
LD4: LD4.2 U6.19 | length 706.4
  Top Layer w6: U6.19@8104.58,4495.46 8143.22,4495.46 8153.17,4505.41 8153.17,4626.61 8141.57,4638.21 8141.57,4748.21 8196.77,4803.41 8397.57,4803.41 8413.57,4787.41 8464.77,4787.41 8501.39,4824.04 LD4.2@8501.39,4825.63
M-ATLK_RX: R48.1 U6.31 | length 483.9
  Top Layer w6: U6.31@8281.76,4337.98 8281.76,4271.98 8249.46,4239.58 8249.46,4170.28 8440.46,3979.28 R48.1@8440.46,3946.58
M-ATLK_TX: R47.1 U6.30 | length 457.3
  Top Layer w6: U6.30@8262.06,4337.98 8262.06,4276.28 8234.66,4248.88 8234.66,4102.88 8366.46,3971.08 R47.1@8366.46,3946.58
M-BOOT0: J9.2 U6.44 | length 154.6
  Top Layer w6: U6.44@8439.26,4534.88 8510.66,4534.88 J9.2@8569.46,4593.68
M-NRST: C22.2 P1.4 U6.7 | length 893.3
  Top Layer w6: U6.7@8262.06,4672.68 8262.06,4619.48 v2(8272.16,4609.38) ; v2(8324.77,4579.01) 8353.97,4579.01 8382.37,4550.61 v2(8382.37,4424.61)
  Bottom Layer w6: C22.2@8273.97,4579.77 8324.01,4579.77 v2(8324.77,4579.01) ; v2(8382.37,4424.61) 8409.57,4397.41 8409.57,4068.77 P1.4@8538.16,3940.18
  Bottom Layer w10: v2(8272.16,4609.38) 8273.97,4607.57 C22.2@8273.97,4579.77
M-SWCLK: P1.3 U6.37 | length 475.2
  Top Layer w6: U6.37@8439.26,4397.04 8484.75,4397.04 v2(8504.37,4377.41)
  Bottom Layer w6: v2(8504.37,4377.41) 8504.37,4333.01 8443.17,4271.81 8443.17,4135.17 P1.3@8538.16,4040.18
M-SWDIO: P1.2 U6.34 | length 376.2
  Top Layer w6: U6.34@8340.8,4337.98 8340.76,4172.56 8373.14,4140.18 P1.2@8538.16,4140.18
M-USB_DM: R12.2 U6.32 | length 1557.9
  Top Layer w6: v2(8289.29,5431.83) 8290.08,5432.61 R12.2@8290.08,5505.16 ; v2(8290.51,4244.08) 8301.46,4255.04 U6.32@8301.46,4337.98
  Bottom Layer w6: v2(8289.29,5431.83) 8270.37,5412.9 8270.37,5061.25 8122.77,4913.65 8122.77,4321.44 8208.23,4235.98 8282.42,4235.98 v2(8290.51,4244.08)
M-USB_DP: R11.2 U6.33 | length 1610.2
  Top Layer w6: R11.2@8238.07,5504.37 8238.07,5432.9 v2(8239.61,5431.36) ; v2(8317.31,4236.99) 8321.16,4240.86 U6.33@8321.16,4337.98
  Bottom Layer w6: v2(8239.61,5431.36) 8258.37,5412.6 8258.37,5066.22 8110.77,4918.62 8110.77,4316.47 8203.26,4223.98 8304.31,4223.98 v2(8317.31,4236.99)
NRST: B1.1 B1.3 C40.1 CN4.7 CN7.7 J2.25 J4.3 J7.5 R46.2 U1.25 | length 7009.8
  Top Layer w6: v2(8292.66,3383.78) 8292.81,3383.93 8292.81,3663.13 8292.66,3662.98 ; v1(8292.66,3645.23) 8292.66,3662.98 ; R46.2@8292.66,3892.68 8292.66,3662.98 ; v2(8616.21,3600.97) 8632.56,3584.61 8738.57,3584.61 8828.03,3674.07 B1.3@8828.03,3728.39 B1.1@9174.49,3728.39 9185.06,3738.98 9298.26,3738.98 C40.1@9331.77,3705.97 9495.26,3705.98 9584.26,3794.98 10439.66,3794.98 10439.66,3796.08 10441.57,3797.96 ; J2.25@10529.17,3267.08 10480.26,3316.08 10480.26,3403.93 10441.57,3442.61 10441.57,3797.96 ; v2(11451.16,4391.98) 11428.2,4391.98 11354.2,4465.98 10846.66,4465.98 10842.76,4461.98 U1.25@10671.86,4462.04 10539.66,4461.98 10441.57,4363.89 10441.57,3797.96 ; v2(11630.21,4440.97) 11659.92,4440.97 11685.51,4466.56 J7.5@12054.81,4466.56
  Bottom Layer w6: CN7.7@8195.43,3166.63 8195.43,3286.55 v2(8292.66,3383.78) ; v1(8292.66,3645.23) 8571.94,3645.23 v2(8616.21,3600.97) ; v2(8879.21,3727.97) 8879.21,4173.95 CN4.7@8933.23,4227.98 ; J2.25@10529.17,3267.08 10579.26,3317.08 10579.26,3420.98 10627.26,3468.98 10803.36,3468.98 10839.86,3505.48 J4.3@10839.86,3565.98 ; v2(11451.16,4391.98) 11581.22,4391.98 v2(11630.21,4440.97)
OTGFS1_D+: CN1.3 CN2.A6 CN2.B6 R30.2 | length 1406.2
  Top Layer w5.98: R30.2@12760.64,5194.62 12785.25,5170.01 12896.06,5170.01 CN1.3@12930.72,5204.67 ; CN2.B6@13120.94,4523.32 v2(13191.63,4523.32)
  Top Layer w6: CN1.3@12930.72,5204.67 12939.2,5204.67 12972.24,5171.63 13200.9,5171.63 13248.97,5123.56 13248.97,4515.74 13217.25,4484.02 v2(13189.95,4484.02) CN2.A6@13120.94,4484.02
  Bottom Layer w5.98: v2(13189.95,4484.02) 13189.95,4521.64 v2(13191.63,4523.32)
OTGFS1_D-: CN1.2 CN2.A7 CN2.B7 R31.2 | length 1410.6
  Top Layer w5.98: R31.2@12760.64,5127.69 12760.64,5127.82 12790.87,5158.04 12898.6,5158.04 CN1.2@12930.72,5125.93 ; CN2.B7@13120.94,4464.32 13067.48,4464.32 13055.8,4475.99 13055.8,4492.81 13066.61,4503.62 CN2.A7@13120.94,4503.62
  Top Layer w6: CN1.2@12930.72,5125.93 12939.2,5125.93 12972.9,5159.63 13195.93,5159.63 13236.97,5118.59 13236.97,4520.71 13220.43,4504.17 13121.49,4504.17 CN2.A7@13120.94,4503.62
PA0: J2.34 J6.1 R19.2 U1.34 | length 3215.2
  Top Layer w6: R19.2@9332.66,3653.98 9372.02,3653.98 9391.72,3673.68 9504.96,3673.68 9601.26,3769.98 v2(10391.16,3769.98) ; U1.34@10671.86,4284.87 10592.84,4284.88 10562.26,4254.23 10562.26,3886.38 10583.26,3865.38 10583.26,3769.97 10583.26,3725.98 10692.26,3616.98 10692.26,3523.98 10717.26,3498.98 10823.26,3498.98 10929.16,3392.98 J2.34@10929.17,3367.08
  Bottom Layer w6: v2(10391.16,3769.98) v2(10583.21,3769.97) ; J2.34@10929.17,3367.08 11058.16,3495.98 11406.26,3495.98 11476.26,3565.98 J6.1@11539.86,3565.98
PA1: J2.35 J6.2 U1.35 | length 2180.2
  Top Layer w6: U1.35@10671.86,4265.19 10613.76,4265.18 10594.63,4246.05 10594.63,3878.41 10611.56,3861.48 10611.56,3728.68 10709.66,3630.58 10867.66,3630.58 10896.26,3601.98 10896.26,3525.98 10978.26,3443.98 10978.26,3318.08 J2.35@11029.17,3267.08
  Bottom Layer w6: J2.35@11029.17,3267.08 11078.26,3315.98 11078.26,3449.98 11102.26,3473.98 11600.16,3473.98 11639.86,3513.58 J6.2@11639.86,3565.98
PA2: J2.36 J5.2 U1.36 | length 3526.8
  Top Layer w6: J2.36@11029.17,3367.08 11029.16,3466.98 10988.26,3507.98 10988.26,3619.98 10962.26,3645.98 10723.16,3645.98 10637.36,3731.78 10637.36,3862.08 10628.51,3870.93 10628.51,4233.83 10640.16,4245.48 U1.36@10671.86,4245.5 10748.11,4245.48 10804.61,4301.98 v2(11285.21,4301.97) ; v2(11472.46,5327.97) 11493.46,5327.97 11499.37,5333.88 11870.76,5333.88 11939.76,5402.88 J5.2@11939.8,5465.97
  Bottom Layer w6: v2(11285.21,4301.97) 11285.21,4830.64 11474.03,5019.47 11474.03,5279.85 11477.58,5283.4 11477.58,5308.44 11474.03,5311.99 11474.03,5326.4 v2(11472.46,5327.97)
PA3: J2.37 J5.1 U1.37 | length 3567.5
  Top Layer w6: J2.37@11129.17,3267.08 11078.26,3318.08 11078.26,3493.98 11092.26,3507.98 11092.26,3613.88 11043.96,3662.18 10789.96,3662.18 10745.76,3706.38 10745.76,4171.68 10745.76,4222.64 10805.1,4281.98 v2(11262.21,4281.97) ; v2@11455.95,5300.35 11497.63,5300.35 11510.26,5312.98 11886.86,5312.98 J5.1@12039.8,5465.97
  Bottom Layer w6: v2(11262.21,4281.97) 11262.21,4829.25 11456.7,5023.74 11456.7,5299.6 v2(11455.91,5300.39)
PA4: J2.40 J6.3 U1.40 | length 1779.9
  Top Layer w6: U1.40@10804.76,4171.68 10804.76,3728.38 10856.46,3676.68 11108.56,3676.68 11180.26,3604.98 11180.26,3481.18 11229.16,3432.28 J2.40@11229.17,3367.08
  Bottom Layer w6: J2.40@11229.17,3367.08 11229.16,3422.98 11260.26,3453.98 11672.26,3453.98 11739.86,3521.58 J6.3@11739.86,3565.98
PA5: J2.41 J3.6 U1.41 | length 2624.8
  Top Layer w6: v2(10845.74,4244.57) 10845.74,4243.88 10824.46,4222.6 10824.46,4171.68 10824.46,3761.68 10895.26,3690.98 11128.16,3690.98 11196.26,3622.98 11196.26,3497.98 11278.26,3415.98 11278.26,3318.08 J2.41@11329.17,3267.08
  Bottom Layer w6: J3.6@10679.86,5465.98 10679.86,5424.38 10772.26,5331.98 10772.26,5041.78 10849.23,4964.8 10849.23,4248.06 v2(10845.74,4244.57)
PA6: J2.42 J3.5 U1.42 | length 2540.2
  Top Layer w6: v2(10868.07,4261.17) 10868.07,4238.25 10844.16,4214.33 10844.16,4171.68 10844.16,3792.98 10931.26,3705.98 11262.26,3705.98 11282.26,3685.98 11282.26,3474.88 11329.16,3427.98 J2.42@11329.17,3367.08
  Bottom Layer w6: J3.5@10779.86,5465.98 10779.86,5409.38 10787.26,5401.98 10787.26,5049.37 10868.07,4968.55 v2(10868.07,4261.17)
PA7: J2.43 J3.4 U1.43 | length 2695.5
  Top Layer w6: v2(10886.92,4232.13) 10886.38,4232.13 10863.86,4209.61 10863.86,4171.68 10863.86,3814.88 10954.76,3723.98 11271.26,3723.98 11300.26,3694.98 11300.26,3489.98 11378.26,3411.98 11378.26,3318.08 J2.43@11429.17,3267.08
  Bottom Layer w6: J3.4@10879.86,5465.98 10879.86,5419.38 10802.26,5341.78 10802.26,5057.48 10886.92,4972.82 v2(10886.92,4232.13)
PA8: J1.28 J5.8 U1.100 | length 1433.4
  Top Layer w6: J5.8@11339.8,5465.97 11339.76,5533.38 11365.66,5559.28 11422.76,5559.28 J1.28@11529.16,5665.68 ; U1.100@11508.56,4776.98 11603.16,4776.98 v2(11657.16,4830.98)
  Bottom Layer w6: J1.28@11529.16,5665.68 11562.68,5632.15 11562.68,5573.01 11585.76,5549.98 11654.26,5549.98 11684.86,5519.38 11684.86,4858.67 v2(11657.16,4830.98)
